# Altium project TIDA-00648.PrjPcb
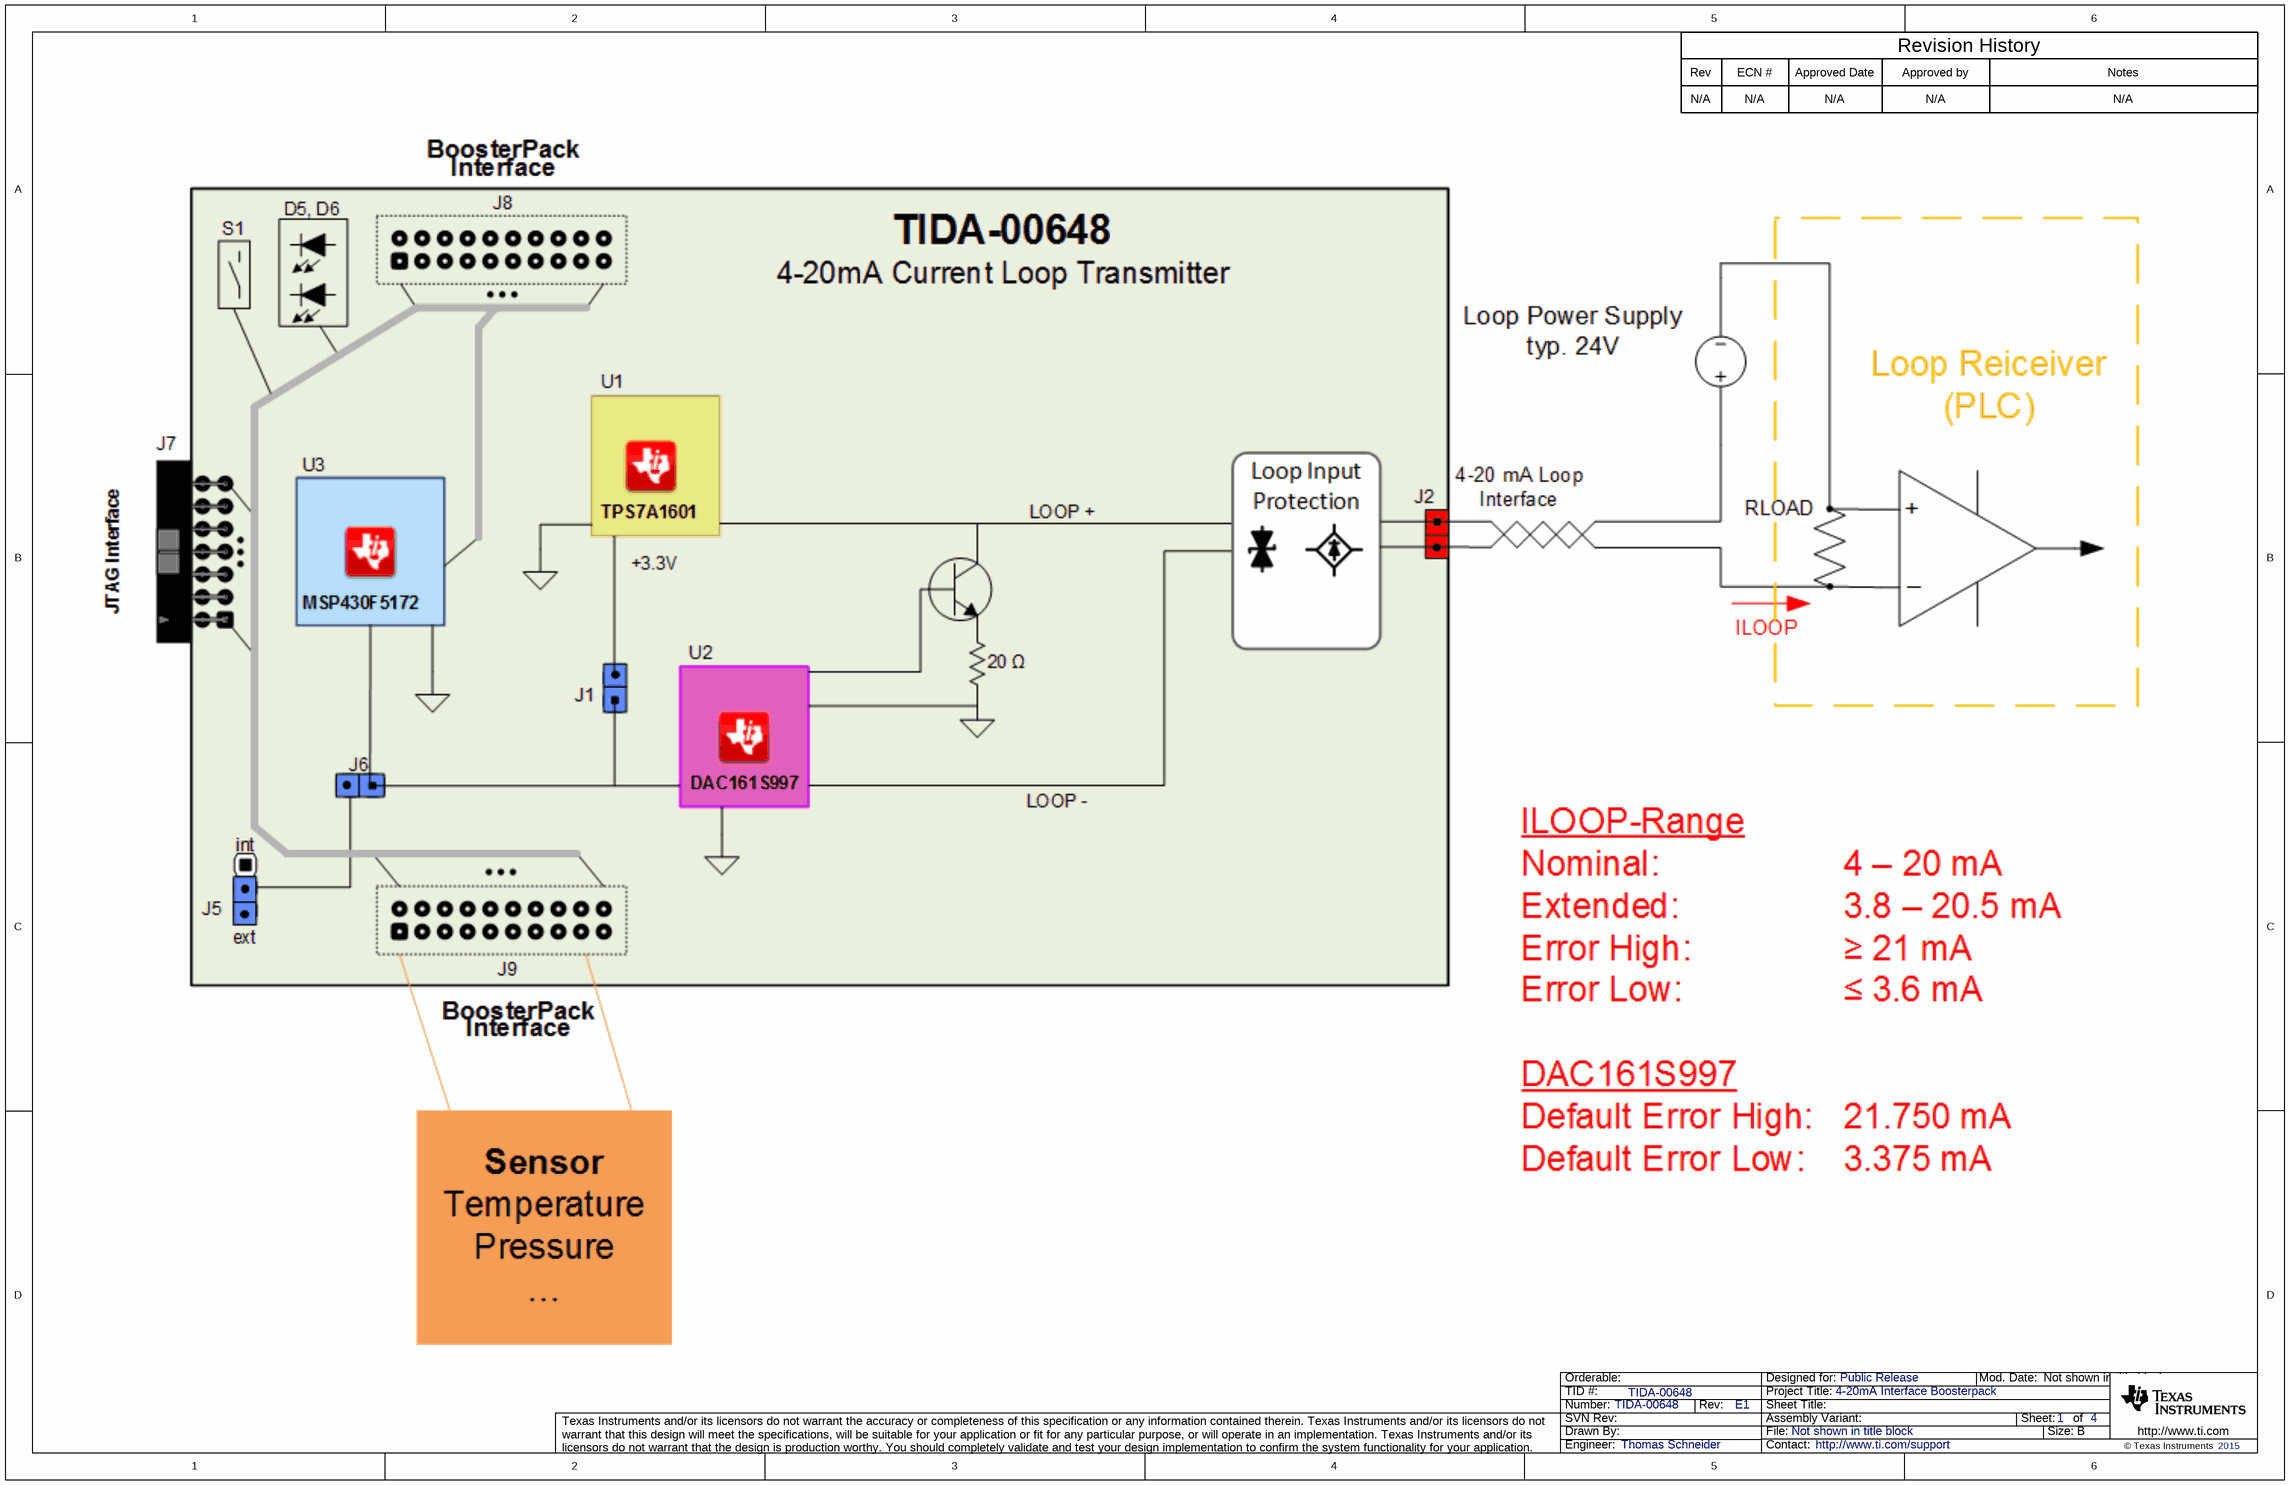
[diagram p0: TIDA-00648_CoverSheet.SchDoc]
CopyrightYear: 2015; PCB_Layout: Thomas Schneider; PCB_Rev: E1; PRJ_Customer: Public Release; PRJ_Engineer: Thomas Schneider; PRJ_Number: TIDA-00648; PRJ_Title: 4-20mA Interface Boosterpack; SCH_Rev: E1; TechSupport: http://www.ti.com/support; TID: TIDA-00648
4 sheets, 92 parts. Net scope: flat (ports and power ports of the same name join across sheets).
Board file: TIDA-00648_EVM.PcbDoc
Sheets:
  TIDA-00648_CoverSheet.SchDoc
  TIDA-00648_DAC.SchDoc
  TIDA-00648_Hardware.SchDoc
  TIDA-00648_MCU.SchDoc

## Sheet TIDA-00648_CoverSheet.SchDoc
size 431 x 279 mm; Date: Not shown in title block; ApprovedBy: Not shown in title block; CheckedBy: Not shown in title block; Author: Not shown in title block; CompanyName: Not shown in title block; Engineer: Not shown in title block; Organization: Not shown in title block; Address1: Not shown in title block; Address2: Not shown in title block; Address3: Not shown in title block; Address4: Not shown in title block; DocumentNumber: 1; Revision: Use project parameter SCH_Rev; SheetNumber: 1; SheetTotal: 4; PageSetup: Record=PageOptions¦CenterHorizontal=True¦CenterVertical=True¦PrintScale=1.00¦XCorrection=1.00¦YCorrection=1.00¦PrintKind=0¦BorderSize=5000000¦LeftOffset=0¦BottomOffset=0¦Orientation=2¦PaperLength=1000¦PaperWidth=1000¦Scale=100¦PaperSource=15¦PrintQuality=600¦MediaType=1¦DitherType=10¦PaperKind=Letter¦PrintScaleMode=1

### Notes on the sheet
- Rev
- N/A
- ECN #
- Approved Date
- Approved by
- Revision History
- Notes

## Sheet TIDA-00648_DAC.SchDoc
size 431 x 279 mm; Date: Not shown in title block; ApprovedBy: Not shown in title block; CheckedBy: Not shown in title block; Author: Not shown in title block; CompanyName: Not shown in title block; Engineer: Not shown in title block; Organization: Not shown in title block; Address1: Not shown in title block; Address2: Not shown in title block; Address3: Not shown in title block; Address4: Not shown in title block; DocumentNumber: 2; Revision: Use project parameter SCH_Rev; SheetNumber: 2; SheetTotal: 4; PageSetup: Record=PageOptions¦CenterHorizontal=True¦CenterVertical=True¦PrintScale=1.00¦XCorrection=1.00¦YCorrection=1.00¦PrintKind=0¦BorderSize=5000000¦LeftOffset=0¦BottomOffset=0¦Orientation=2¦PaperLength=1000¦PaperWidth=1000¦Scale=100¦PaperSource=15¦PrintQuality=600¦MediaType=1¦DitherType=10¦PaperKind=Letter¦PrintScaleMode=1
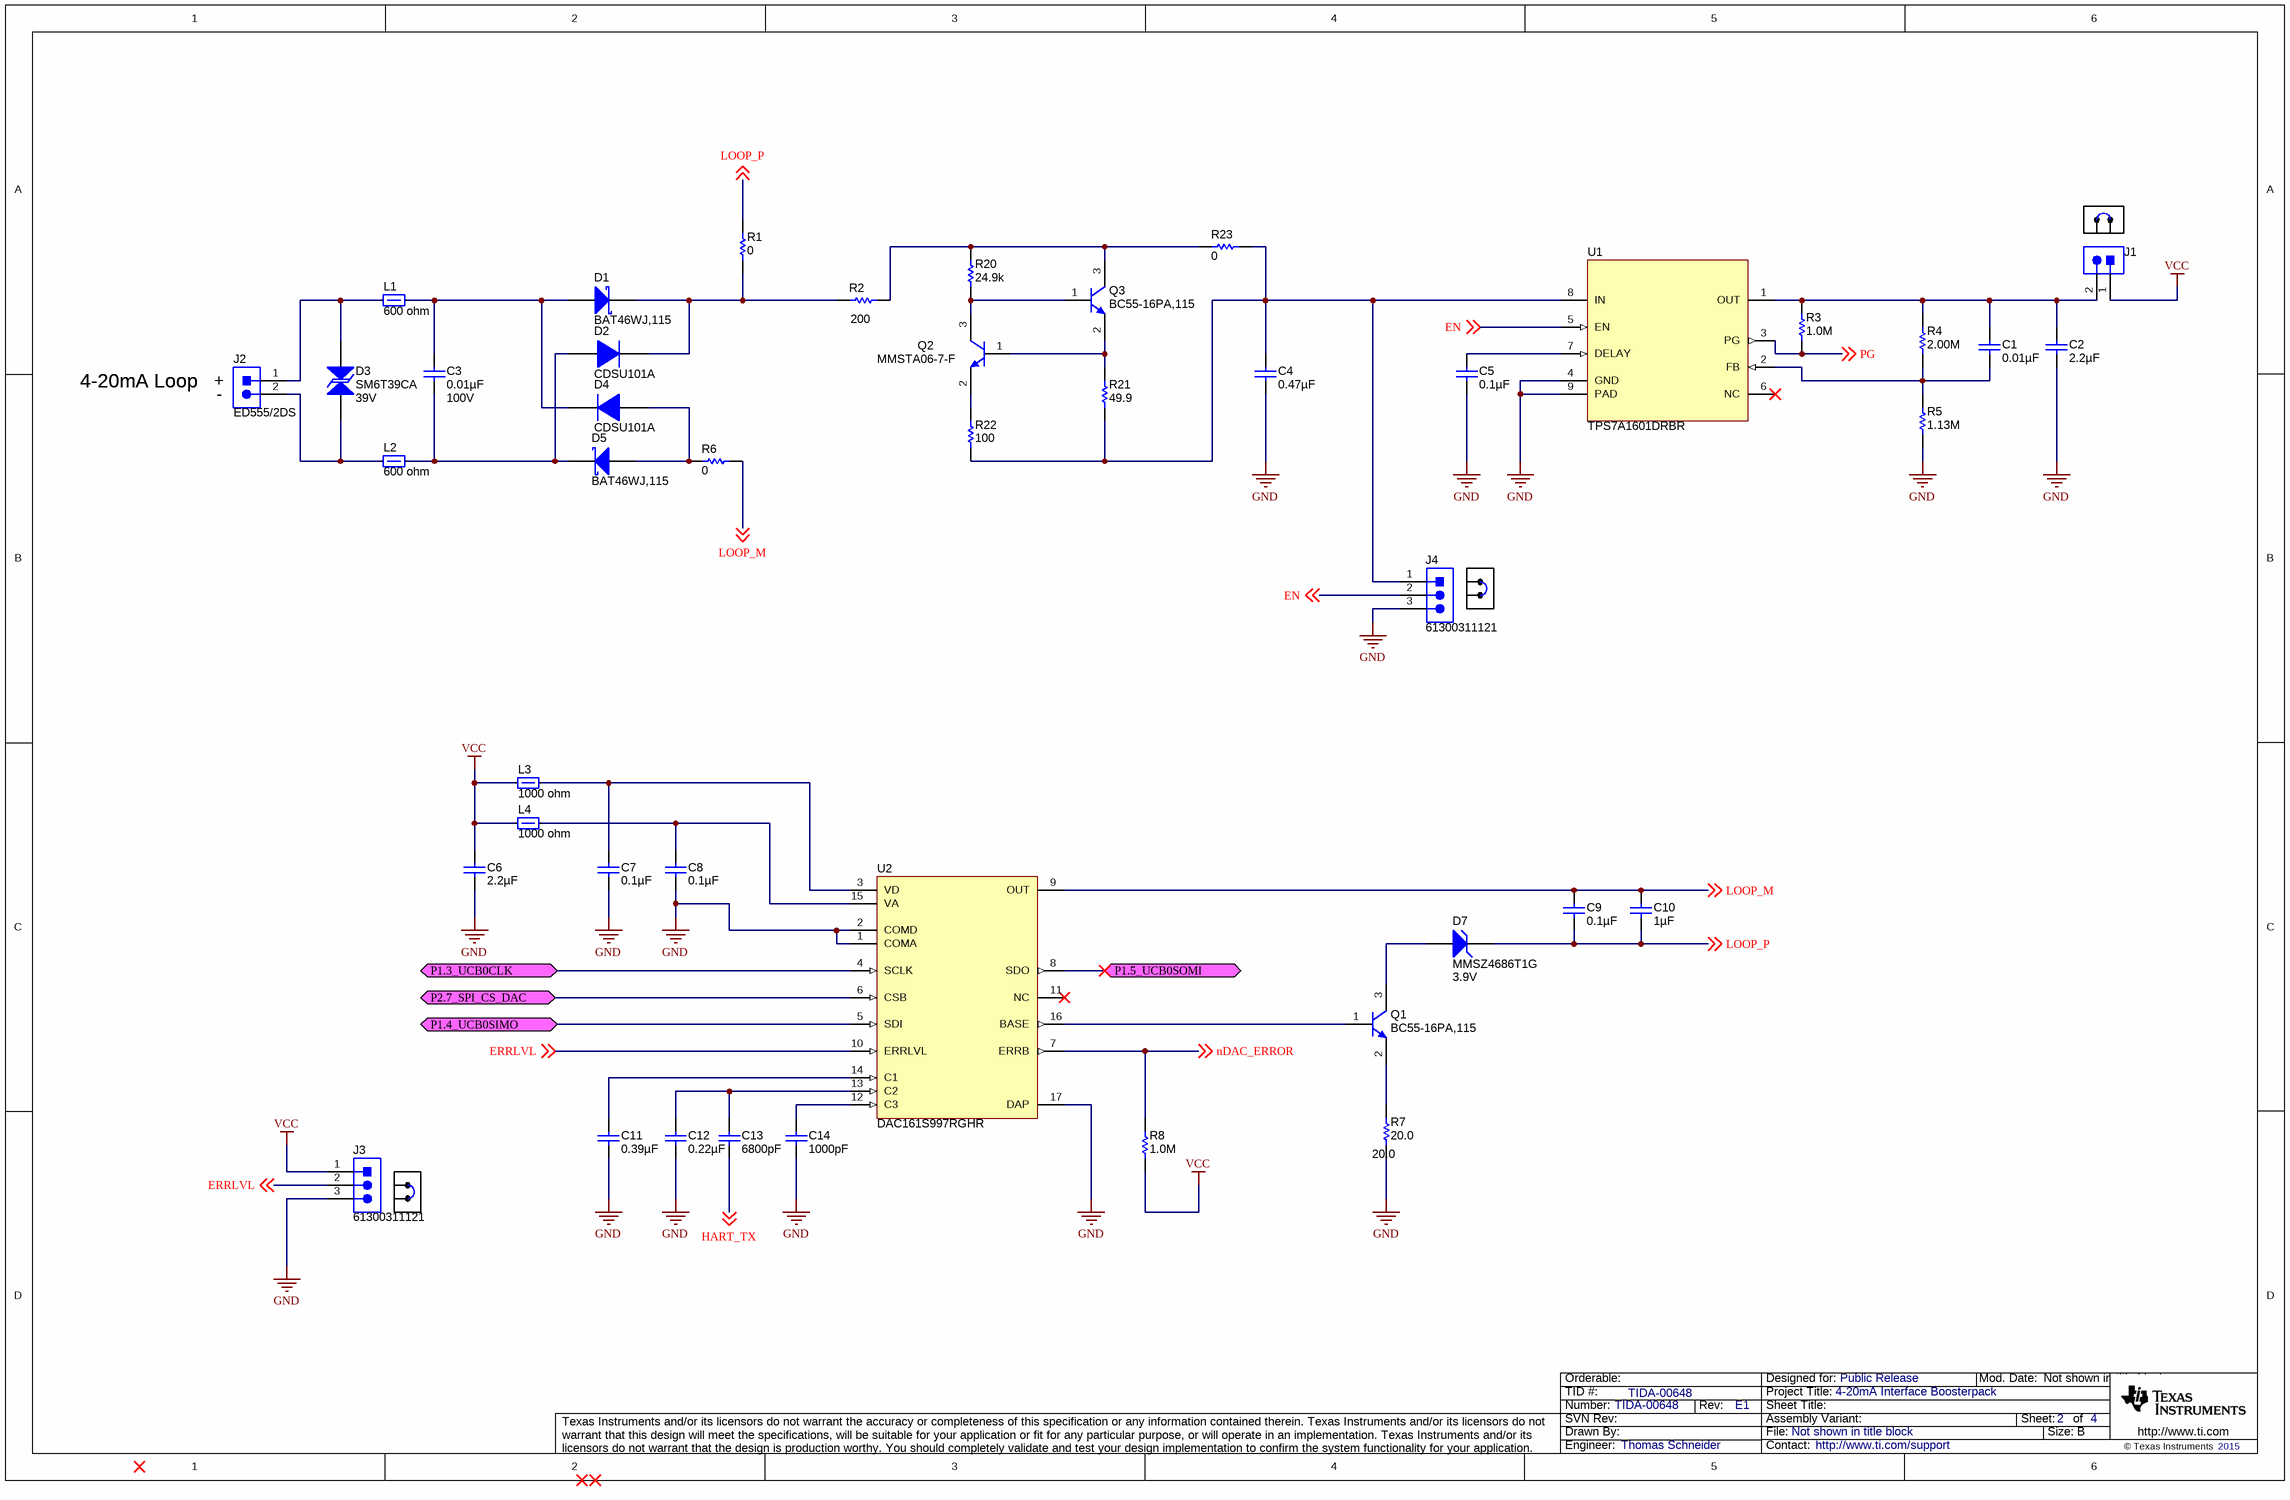
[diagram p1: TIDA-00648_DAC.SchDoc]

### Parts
C1  ValueDisplayed: 0.01µF  [0402]  (hidden comment: GRM155R61A103KA01D)
C2  ValueDisplayed: 2.2µF  [0402]  (hidden comment: C1005X5R1C225K050BC)
C3  ValueDisplayed: 0.01µF  Value2: 100V  [0603]  (hidden comment: C1608X7R2A103K)
C4  ValueDisplayed: 0.47µF  [0805]  (hidden comment: GRM21BR72A474KA73L)
C5  ValueDisplayed: 0.1µF  [0402]  (hidden comment: GRM155R61A104KA01D)
C6  ValueDisplayed: 2.2µF  [0402]  (hidden comment: C1005X5R1C225K050BC)
C7  ValueDisplayed: 0.1µF  [0402]  (hidden comment: C1005X5R0J104K)
C8  ValueDisplayed: 0.1µF  [0402]  (hidden comment: C1005X5R0J104K)
C9  ValueDisplayed: 0.1µF  [1206]  (hidden comment: 12061C104JAT2A)
C10  ValueDisplayed: 1µF  [1206]  (hidden comment: GRM31CR72A105KA01L)
C11  ValueDisplayed: 0.39µF  [0402]  (hidden comment: GRM155R61A394KE15D)
C12  ValueDisplayed: 0.22µF  [0402]  (hidden comment: GRM155R60J224KE01D)
C13  ValueDisplayed: 6800pF  [0402]  (hidden comment: GRM155R71E682KA01D)
C14  ValueDisplayed: 1000pF  [0402]  (hidden comment: GRM155R60J102KA01D)
D1  BAT46WJ,115  [SOD-323F]
D2  CDSU101A  [SOD-523F]
D3  SM6T39CA  value 39V  [SMB]
D4  CDSU101A  [SOD-523F]
D5  BAT46WJ,115  [SOD-323F]
D7  MMSZ4686T1G  value 3.9V  [SOD-123]
J1  61300211121  [WURTH_61300211121]  (value not drawn)
J2  ED555/2DS  [TERM_BLK_ED555-2DS]
J3  61300311121  [WURTH_61300311121]
J4  61300311121  [WURTH_61300311121]
L1  value 600 ohm  [1206]  (hidden comment: MI1206K601R-10)
L2  value 600 ohm  [1206]  (hidden comment: MI1206K601R-10)
L3  value 1000 ohm  [0402]  (hidden comment: BLM15HG102SN1D)
L4  value 1000 ohm  [0402]  (hidden comment: BLM15HG102SN1D)
Q1  BC55-16PA,115  [SOT1061]
Q2  MMSTA06-7-F  [SOT-323]
Q3  BC55-16PA,115  [SOT1061]
R1  ValueDisplayed: 0  [0603]  (hidden comment: CRCW06030000Z0EA)
R2  ValueDisplayed: 200  [1206]  (hidden comment: CRCW1206200RFKEA)
R3  ValueDisplayed: 1.0M  [0402]  (hidden comment: CRCW04021M00JNED)
R4  ValueDisplayed: 2.00M  [0402]  (hidden comment: CRCW04022M00FKED)
R5  ValueDisplayed: 1.13M  [0402]  (hidden comment: CRCW04021M13FKED)
R6  ValueDisplayed: 0  [0603]  (hidden comment: CRCW06030000Z0EA)
R7  value 20.0  [0603]  (hidden comment: CRCW060320R0FKEA)
R8  ValueDisplayed: 1.0M  [0402]  (hidden comment: CRCW04021M00JNED)
R20  ValueDisplayed: 24.9k  [0603]  (hidden comment: CRCW060324K9FKEA)
R21  ValueDisplayed: 49.9  [1206]  (hidden comment: CRCW120649R9FKEA)
R22  ValueDisplayed: 100  [0603]  (hidden comment: CRCW0603100RFKEA)
R23  ValueDisplayed: 0  [0603]  (hidden comment: CRCW06030000Z0EA)
SH-J1  969102-0000-DA  [SNT-100-BK-G]  (value not drawn)
SH-J2  969102-0000-DA  [SNT-100-BK-G]  (value not drawn)
SH-J3  969102-0000-DA  [SNT-100-BK-G]  (value not drawn)
U1  TPS7A1601DRBR  [DRB0008B]
U2  DAC161S997RGHR  [RGH0016A]

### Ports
P1.3_UCB0CLK (bidir), P1.4_UCB0SIMO (bidir), P1.5_UCB0SOMI (bidir), P2.7_SPI_CS_DAC (bidir)

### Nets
GND: C2.2 C4.2 C5.2 C6.2 C7.2 C8.2 C11.2 C12.2 C14.2 J3.3 J4.3 R5.1 R7.1 U1.4(GND) U1.9(PAD) U2.1(COMA) U2.2(COMD) U2.17(DAP)
VCC: C6.1 J1.1 J3.1 L3.1 L4.1 R8.1
EN: J4.2 U1.5(EN) ; off-sheet EN
ERRLVL: J3.2 U2.10(ERRLVL) ; off-sheet ERRLVL
HART_TX: C13.2 ; off-sheet HART_TX
LOOP_M: C9.2 C10.2 R6.1 U2.9(OUT) ; off-sheet LOOP_M
LOOP_P: C9.1 C10.1 D7.1(K) R1.2 ; off-sheet LOOP_P
nDAC_ERROR: R8.2 U2.7(ERRB) ; off-sheet nDAC_ERROR
P1.3_UCB0CLK: U2.4(SCLK) ; port P1.3_UCB0CLK
P1.4_UCB0SIMO: U2.5(SDI) ; port P1.4_UCB0SIMO
P1.5_UCB0SOMI: U2.8(SDO) ; port P1.5_UCB0SOMI
P2.7_SPI_CS_DAC: U2.6(CSB) ; port P2.7_SPI_CS_DAC
PG: R3.1 U1.3(PG) ; off-sheet PG
NetC1_1: C1.1 C2.1 J1.2 R3.2 R4.2 U1.1(OUT)
NetC1_2: C1.2 R4.1 R5.2 U1.2(FB)
NetC3_1: C3.1 D1.2(A) D4.1(K) L1.2
NetC3_2: C3.2 D2.2(A) D5.1(K) L2.2
NetC4_1: C4.1 J4.1 R21.1 R22.1 R23.2 U1.8(IN)
NetC5_1: C5.1 U1.7(DELAY)
NetC7_1: C7.1 L3.2 U2.3(VD)
NetC8_1: C8.1 L4.2 U2.15(VA)
NetC11_1: C11.1 U2.14(C1)
NetC12_1: C12.1 C13.1 U2.13(C2)
NetC14_1: C14.1 U2.12(C3)
NetD1_1: D1.1(K) D2.1(K) R1.1 R2.1
NetD3_1: D3.1 J2.1 L1.1
NetD3_2: D3.2 J2.2 L2.1
NetD4_2: D4.2(A) D5.2(A) R6.2
NetD7_2: D7.2(A) Q1.3(C)
NetQ1_1: Q1.1(B) U2.16(BASE)
NetQ1_2: Q1.2(E) R7.2
NetQ2_1: Q2.1(B) Q3.2(E) R21.2
NetQ2_2: Q2.2(E) R22.2
NetQ2_3: Q2.3(C) Q3.1(B) R20.1
NetQ3_3: Q3.3(C) R2.2 R20.2 R23.1

Not connected (* = marked no-connect by the designer): U1 6(NC)*; U2 11(NC)*

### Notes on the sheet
- 4-20mA Loop
- (near J2) +
- (near J2) -

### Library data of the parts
C1 = GRM155R61A103KA01D: CAP, CERM, 0.01 µF, 10 V, +/- 10%, X5R, 0402; Manufacturer: MuRata; Polarized: N; CompType: Capacitor; Value: 0.01uF; U/M: EA; Cap_F: 0.00000001; Tolerance_%: 10; Value1: Unknown; Value2: 10V; TaMin_C: -55; TaMax_C: 85; AEC Category: Q200
C2 C6 = C1005X5R1C225K050BC: CAP, CERM, 2.2 µF, 16 V, +/- 10%, X5R, 0402; Manufacturer: TDK; Polarized: N; CompType: Capacitor; Value: 2.2uF; U/M: EA; Cap_F: 0.0000022; Tolerance_%: 10; Value1: Unknown; VDC_V: 16; Value2: 16V; TaMin_C: -55; TaMax_C: 85; AEC Category: Q200
C3 = C1608X7R2A103K: CAP, CERM, 0.01 µF, 100 V, +/- 10%, X7R, 0603; Manufacturer: TDK; Polarized: N; CompType: Capacitor; Value: 0.01uF; U/M: EA; Cap_F: 0.00000001; Tolerance_%: 10; ESR_ohm: 0.0661; Value1: 0.0661 ohm; VDC_V: 100; TaMin_C: -55; TaMax_C: 125; AEC Category: Q200
C4 = GRM21BR72A474KA73L: CAP, CERM, 0.47 µF, 100 V, +/- 10%, X7R, 0805; Manufacturer: MuRata; Polarized: N; CompType: Capacitor; Value: 0.47uF; U/M: EA; Cap_F: 0.00000047; Tolerance_%: 10; Value1: Unknown; VDC_V: 100; Value2: 100V; TaMin_C: -55; TaMax_C: 125; AEC Category: Q200
C5 = GRM155R61A104KA01D: CAP, CERM, 0.1 µF, 10 V, +/- 10%, X5R, 0402; Manufacturer: MuRata; Polarized: N; CompType: Capacitor; Value: 0.1uF; U/M: EA; Cap_F: 0.0000001; Tolerance_%: 10; Value1: Unknown; Value2: 10V; TaMin_C: -55; TaMax_C: 85; AEC Category: Q200
C7 C8 = C1005X5R0J104K: CAP, CERM, 0.1 µF, 6.3 V, +/- 10%, X5R, 0402; Manufacturer: TDK; Polarized: N; CompType: Capacitor; Value: 0.1uF; U/M: EA; Cap_F: 0.0000001; Tolerance_%: 10; ESR_ohm: 0.0186; Value1: 0.0186 ohm; VDC_V: 6.3; Value2: 6.3V; TaMin_C: -55; TaMax_C: 85; AEC Category: Q200
C9 = 12061C104JAT2A: CAP, CERM, 0.1 µF, 100 V, +/- 5%, X7R, 1206; Manufacturer: AVX; Polarized: N; CompType: Capacitor; Value: 0.1uF; U/M: EA; Cap_F: 0.0000001; Tolerance_%: 5; ESR_ohm: 0.037; Value1: 0.037 ohm; VDC_V: 100; Value2: 100V; TaMin_C: -55; TaMax_C: 125; AEC Category: Q200
C10 = GRM31CR72A105KA01L: CAP, CERM, 1 µF, 100 V, +/- 10%, X7R, 1206; Manufacturer: MuRata; Polarized: N; CompType: Capacitor; Value: 1uF; U/M: EA; Cap_F: 0.000001; Tolerance_%: 10; Value1: Unknown; VDC_V: 100; Value2: 100V; TaMin_C: -55; TaMax_C: 125; Cap_Case: 2220; AEC Category: Q200
C11 = GRM155R61A394KE15D: CAP, CERM, 0.39 µF, 10 V, +/- 10%, X5R, 0402; Manufacturer: MuRata; Polarized: N; CompType: Capacitor; Value: 0.39uF; U/M: EA; Cap_F: 0.00000039; Tolerance_%: 10; Value1: Unknown; Value2: 10V; TaMin_C: -55; TaMax_C: 85; AEC Category: Q200
C12 = GRM155R60J224KE01D: CAP, CERM, 0.22 µF, 6.3 V, +/- 10%, X5R, 0402; Manufacturer: MuRata; Polarized: N; CompType: Capacitor; Value: 0.22uF; U/M: EA; Cap_F: 0.00000022; Tolerance_%: 10; Value1: Unknown; VDC_V: 6.3; Value2: 6.3V; TaMin_C: -55; TaMax_C: 85; AEC Category: Q200
C13 = GRM155R71E682KA01D: CAP, CERM, 6800 pF, 25 V, +/- 10%, X7R, 0402; Manufacturer: MuRata; Polarized: N; CompType: Capacitor; Value: 6800pF; U/M: EA; Cap_F: 0.0000000068; Tolerance_%: 10; Value1: Unknown; VDC_V: 25; Value2: 25V; TaMin_C: -55; TaMax_C: 125; AEC Category: Q200
C14 = GRM155R60J102KA01D: CAP, CERM, 1000 pF, 6.3 V, +/- 10%, X5R, 0402; Manufacturer: MuRata; Polarized: N; CompType: Capacitor; Value: 1000pF; U/M: EA; Cap_F: 0.000000001; Tolerance_%: 10; Value1: Unknown; VDC_V: 6.3; Value2: 6.3V; TaMin_C: -55; TaMax_C: 85; AEC Category: Q200
D1 D5 = BAT46WJ,115: Diode, Schottky, 100 V, 0.25 A, SOD-323F; Manufacturer: NXP Semiconductor; U/M: EA; Vf_V: 0.85; Value: 100V; Value1: 0.25A; Value2: 0.85V; Io_A: 0.25; Vr_V: 100; TJmax_C: 150; AEC Category: Q101
D2 D4 = CDSU101A: Diode, Switching, 90 V, 0.1 A, SOD-523F; Manufacturer: Comchip Technology; U/M: EA; Vf_V: 1; Value: 90V; Value1: 0.1A; Value2: 1V; Io_A: 0.1; Vr_V: 90; TJmax_C: 125; AEC Category: Q101
D3 = SM6T39CA: Diode, TVS, Bi, 39 V, 600 W, SMB; Manufacturer: STMicroelectronics; U/M: EA; Power_W: 600; Value1: 600W; RJA_CperW: 100; Vr_V: 39; AEC Category: Q101
D7 = MMSZ4686T1G: Diode, Zener, 3.9 V, 500 mW, SOD-123; Manufacturer: ON Semiconductor; U/M: EA; Power_W: 0.5; Vz_V: 3.9; Value1: 0.5W; RJA_CperW: 340; SymbolCreator: a0412235; AEC Category: Q101
J1 = 61300211121: Header, 2.54 mm, 2x1, Gold, TH; Manufacturer: Wurth Elektronik; SymbolCreator: a0412235; U/M: EA
J2 = ED555/2DS: Terminal Block, 6A, 3.5mm Pitch, 2-Pos, TH; Manufacturer: On-Shore Technology; SymbolCreator: a0412235; CompType: Connector; U/M: EA
J3 J4 = 61300311121: Header, 2.54 mm, 3x1, Gold, TH; Manufacturer: Wurth Elektronik; SymbolCreator: a0799628; U/M: EA
L1 L2 = MI1206K601R-10: Ferrite Bead, 600 ohm @ 100 MHz, 1.5 A, 1206; Manufacturer: Laird-Signal Integrity Products; Imax_A: 1.5; DCR_ohm: 0.08; Value1: 0.08 ohm; Value2: 1.5A; ZTyp@100MHz_Ohm: 600; Ztyp@1GHz_Ohm: 130
L3 L4 = BLM15HG102SN1D: Ferrite Bead, 1000 ohm @ 100 MHz, 0.25 A, 0402; Manufacturer: MuRata; Imax_A: 0.25; DCR_ohm: 1.1; Value1: 1.1 ohm; Value2: 0.25A; ZTyp@100MHz_Ohm: 1000
Q1 = BC55-16PA,115, NXP Semiconductor: Transistor, NPN, 60 V, 1 A, AEC-Q101, SOT1061; PNP: 0; NPN: 1; Vceo_V: 60; Vcesat1_V: 0.5; Value: 60 V; Value1: 1 A; HfeMax: 250; TaMin_C: -55; TaMax_C: 150; CompType: BJT; U/M: EA; AEC Category: Q101; AEC Qualified: Y
Q2 = MMSTA06-7-F, Diodes Inc.: Transistor, NPN, 80 V, 0.5 A, SOT-323; CompType: BJT; PNP: 0; NPN: 1; Vceo_V: 80; Vcesat1_V: 0.25; Value: 80 V; IcRated_A: 0.5; Value1: 0.5 A; TaMin_C: -55; TaMax_C: 150; U/M: EA; AEC Category: Q101
Q3 = BC55-16PA,115, NXP Semiconductor: Transistor, NPN, 60 V, 1 A, AEC-Q101, SOT1061; CompType: BJT; PNP: 0; NPN: 1; Vceo_V: 60; Vcesat1_V: 0.5; Value: 60 V; Value1: 1 A; HfeMax: 250; TaMin_C: -55; TaMax_C: 150; U/M: EA; AEC Category: Q101; AEC Qualified: Y
R1 R6 R23 = CRCW06030000Z0EA: RES, 0, 5%, 0.1 W, 0603; Manufacturer: Vishay-Dale; CompType: Resistor; Value: 0; Value_Code: 0000; Tolerance_%: 5; Power_W: 0.1; Value2: 0.1W; VDC_V: 75; TempCo: 200 ppm/C; EIA_Code: E24; U/M: EA; AEC Category: Q200
R2 = CRCW1206200RFKEA: RES, 200, 1%, 0.25 W, 1206; Manufacturer: Vishay-Dale; CompType: Resistor; Value: 200; Value_Code: 200R; Tolerance_%: 1; Power_W: 0.25; Value2: 0.25W; TempCo: 100 ppm/C; EIA_Code: E96; U/M: EA; AEC Category: Q200
R3 R8 = CRCW04021M00JNED: RES, 1.0 M, 5%, 0.063 W, 0402; Manufacturer: Vishay-Dale; CompType: Resistor; Value: 1.0Meg; Res_ohm: 1000000; Value_Code: 1M00; Tolerance_%: 5; Power_W: 0.063; Value2: 0.063W; VDC_V: 50; TempCo: 200 ppm/C; EIA_Code: E24; U/M: EA; AEC Category: Q200
R4 = CRCW04022M00FKED: RES, 2.00 M, 1%, 0.063 W, 0402; Manufacturer: Vishay-Dale; CompType: Resistor; Value: 2.00Meg; Res_ohm: 2000000; Value_Code: 2M00; Tolerance_%: 1; Power_W: 0.063; Value2: 0.063W; VDC_V: 50; TempCo: 100 ppm/C; EIA_Code: E96; U/M: EA; AEC Category: Q200
R5 = CRCW04021M13FKED: RES, 1.13 M, 1%, 0.063 W, 0402; Manufacturer: Vishay-Dale; CompType: Resistor; Value: 1.13Meg; Res_ohm: 1130000; Value_Code: 1M13; Tolerance_%: 1; Power_W: 0.063; Value2: 0.063W; VDC_V: 50; TempCo: 100 ppm/C; EIA_Code: E96; U/M: EA; AEC Category: Q200
R7 = CRCW060320R0FKEA: RES, 20.0, 1%, 0.1 W, 0603; Manufacturer: Vishay-Dale; CompType: Resistor; Res_ohm: 20; Value_Code: 20R0; Tolerance_%: 1; Power_W: 0.1; Value2: 0.1W; VDC_V: 75; TempCo: 100 ppm/C; EIA_Code: E96; U/M: EA; AEC Category: Q200
R20 = CRCW060324K9FKEA: RES, 24.9 k, 1%, 0.1 W, 0603; Manufacturer: Vishay-Dale; CompType: Resistor; Value: 24.9k; Res_ohm: 24900; Value_Code: 24k9; Tolerance_%: 1; Power_W: 0.1; Value2: 0.1W; VDC_V: 75; TempCo: 100 ppm/C; EIA_Code: E96; U/M: EA; AEC Category: Q200
R21 = CRCW120649R9FKEA: RES, 49.9, 1%, 0.25 W, 1206; Manufacturer: Vishay-Dale; CompType: Resistor; Value: 49.9; Value_Code: 49R9; Tolerance_%: 1; Power_W: 0.25; Value2: 0.25W; VDC_V: 200; TempCo: 100 ppm/C; EIA_Code: E96; U/M: EA; AEC Category: Q200
R22 = CRCW0603100RFKEA: RES, 100, 1%, 0.1 W, 0603; Manufacturer: Vishay-Dale; CompType: Resistor; Value: 100; Value_Code: 100R; Tolerance_%: 1; Power_W: 0.1; Value2: 0.1W; VDC_V: 75; TempCo: 100 ppm/C; EIA_Code: E96; U/M: EA; AEC Category: Q200
SH-J1-SH-J3 = 969102-0000-DA: Shunt, 100mil, Gold plated, Black; Manufacturer: 3M; Alternate Manufacturer: Samtec; Value: 1x2; Note: You can "mate" this to a header by matching the designator.  i.e. use SH-J3 for header J3
U1 = TPS7A1601DRBR: 60-V, 5-μA IQ, 100-mA, Low-Dropout Voltage Regulator with Enable and Power-Good, DRB0008B; Alternate Manufacturer: Texas Instruments; Alternate PartNumber: TPS7A1601DRBT; SymbolCreator: a0411947; CompType: IC; U/M: EA
U2 = DAC161S997RGHR: 16-bit SPI Programmable DAC for 4-20mA Loops, RGH0016A; Alternate Manufacturer: Texas Instruments; Alternate PartNumber: DAC161S997RGHT; SymbolCreator: x0208325; CompType: IC; U/M: EA

## Sheet TIDA-00648_Hardware.SchDoc
size 431 x 279 mm; Date: Not shown in title block; ApprovedBy: Not shown in title block; CheckedBy: Not shown in title block; Author: Not shown in title block; CompanyName: Not shown in title block; Engineer: Not shown in title block; Organization: Not shown in title block; Address1: Not shown in title block; Address2: Not shown in title block; Address3: Not shown in title block; Address4: Not shown in title block; DocumentNumber: 4; Revision: Use project parameter SCH_Rev; SheetNumber: 4; SheetTotal: 4; PageSetup: Record=PageOptions¦CenterHorizontal=True¦CenterVertical=True¦PrintScale=1.00¦XCorrection=1.00¦YCorrection=1.00¦PrintKind=0¦BorderSize=5000000¦LeftOffset=0¦BottomOffset=0¦Orientation=2¦PaperLength=1000¦PaperWidth=1000¦Scale=100¦PaperSource=15¦PrintQuality=600¦MediaType=1¦DitherType=10¦PaperKind=Letter¦PrintScaleMode=1
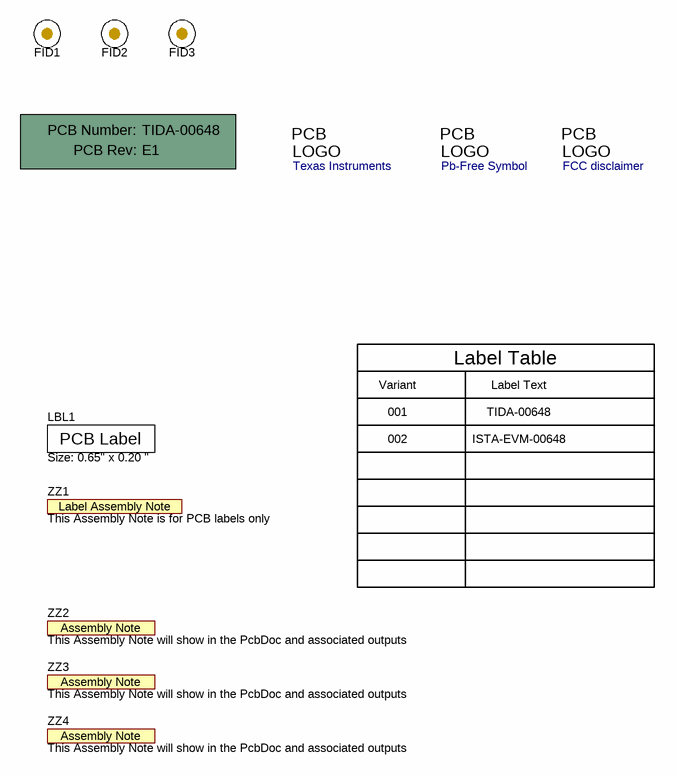
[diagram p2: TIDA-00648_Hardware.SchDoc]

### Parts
!PCB1  Printed Circuit Board  (value not drawn)  (mechanical)
FID1  Fiducial  [Fiducial10-20]  (value not drawn)
FID2  Fiducial  [Fiducial10-20]  (value not drawn)
FID3  Fiducial  [Fiducial10-20]  (value not drawn)
LBL1  Size: 0.65" x 0.20 "  [Label_650x200]
Logo1  Texas Instruments  [TI_Symbol_Overlay_Small]  (no BOM)
Logo2  Pb-Free Symbol  [Pb-Free_Overlay_Small]  (no BOM)
Logo3  FCC disclaimer  [FCC_disclaimer]  (no BOM)
ZZ1  This Assembly Note is for PCB labels only  [AssemblyNoteLabel]  (no BOM)
ZZ2  This Assembly Note will show in the PcbDoc and associated outputs  [AssemblyNote]  (no BOM)
ZZ3  This Assembly Note will show in the PcbDoc and associated outputs  [AssemblyNote]  (no BOM)
ZZ4  This Assembly Note will show in the PcbDoc and associated outputs  [AssemblyNote]  (no BOM)

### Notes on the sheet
- Variant
- Label Table
- Label Text
- 001
- 002
- TIDA-00648
- ISTA-EVM-00648

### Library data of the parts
!PCB1 = PCB: Manufacturer: Any; PartNumber: TIDA-00648; SymbolCreator: a0412235
FID1-FID3 = Fiducial: Fiducial mark.  There is nothing to buy or mount.; SymbolCreator: codlsc
LBL1 = THT-14-423-10: Thermal Transfer Printable Labels, 0.650" W x 0.200" H - 10,000 per roll; Manufacturer: Brady; SymbolCreator: a0412235; CompType: Label
Logo1 = TI_Logo: Texas Instrument Corporate Signature; SymbolCreator: a0412235
Logo2 = Pb-Free: SymbolCreator: a0412235
Logo3 = FCC_disclaimer: SymbolCreator: codlsc
ZZ1 = AssemblyNoteLabel: SymbolCreator: a0412235
ZZ2-ZZ4 = AssemblyNote: SymbolCreator: codlsc

## Sheet TIDA-00648_MCU.SchDoc
size 431 x 279 mm; Date: Not shown in title block; ApprovedBy: Not shown in title block; CheckedBy: Not shown in title block; Author: Not shown in title block; CompanyName: Not shown in title block; Engineer: Not shown in title block; Organization: Not shown in title block; Address1: Not shown in title block; Address2: Not shown in title block; Address3: Not shown in title block; Address4: Not shown in title block; DocumentNumber: 3; Revision: Use project parameter SCH_Rev; SheetNumber: 3; SheetTotal: 4; PageSetup: Record=PageOptions¦CenterHorizontal=True¦CenterVertical=True¦PrintScale=1.00¦XCorrection=1.00¦YCorrection=1.00¦PrintKind=0¦BorderSize=5000000¦LeftOffset=0¦BottomOffset=0¦Orientation=2¦PaperLength=1000¦PaperWidth=1000¦Scale=100¦PaperSource=15¦PrintQuality=600¦MediaType=1¦DitherType=10¦PaperKind=Letter¦PrintScaleMode=1
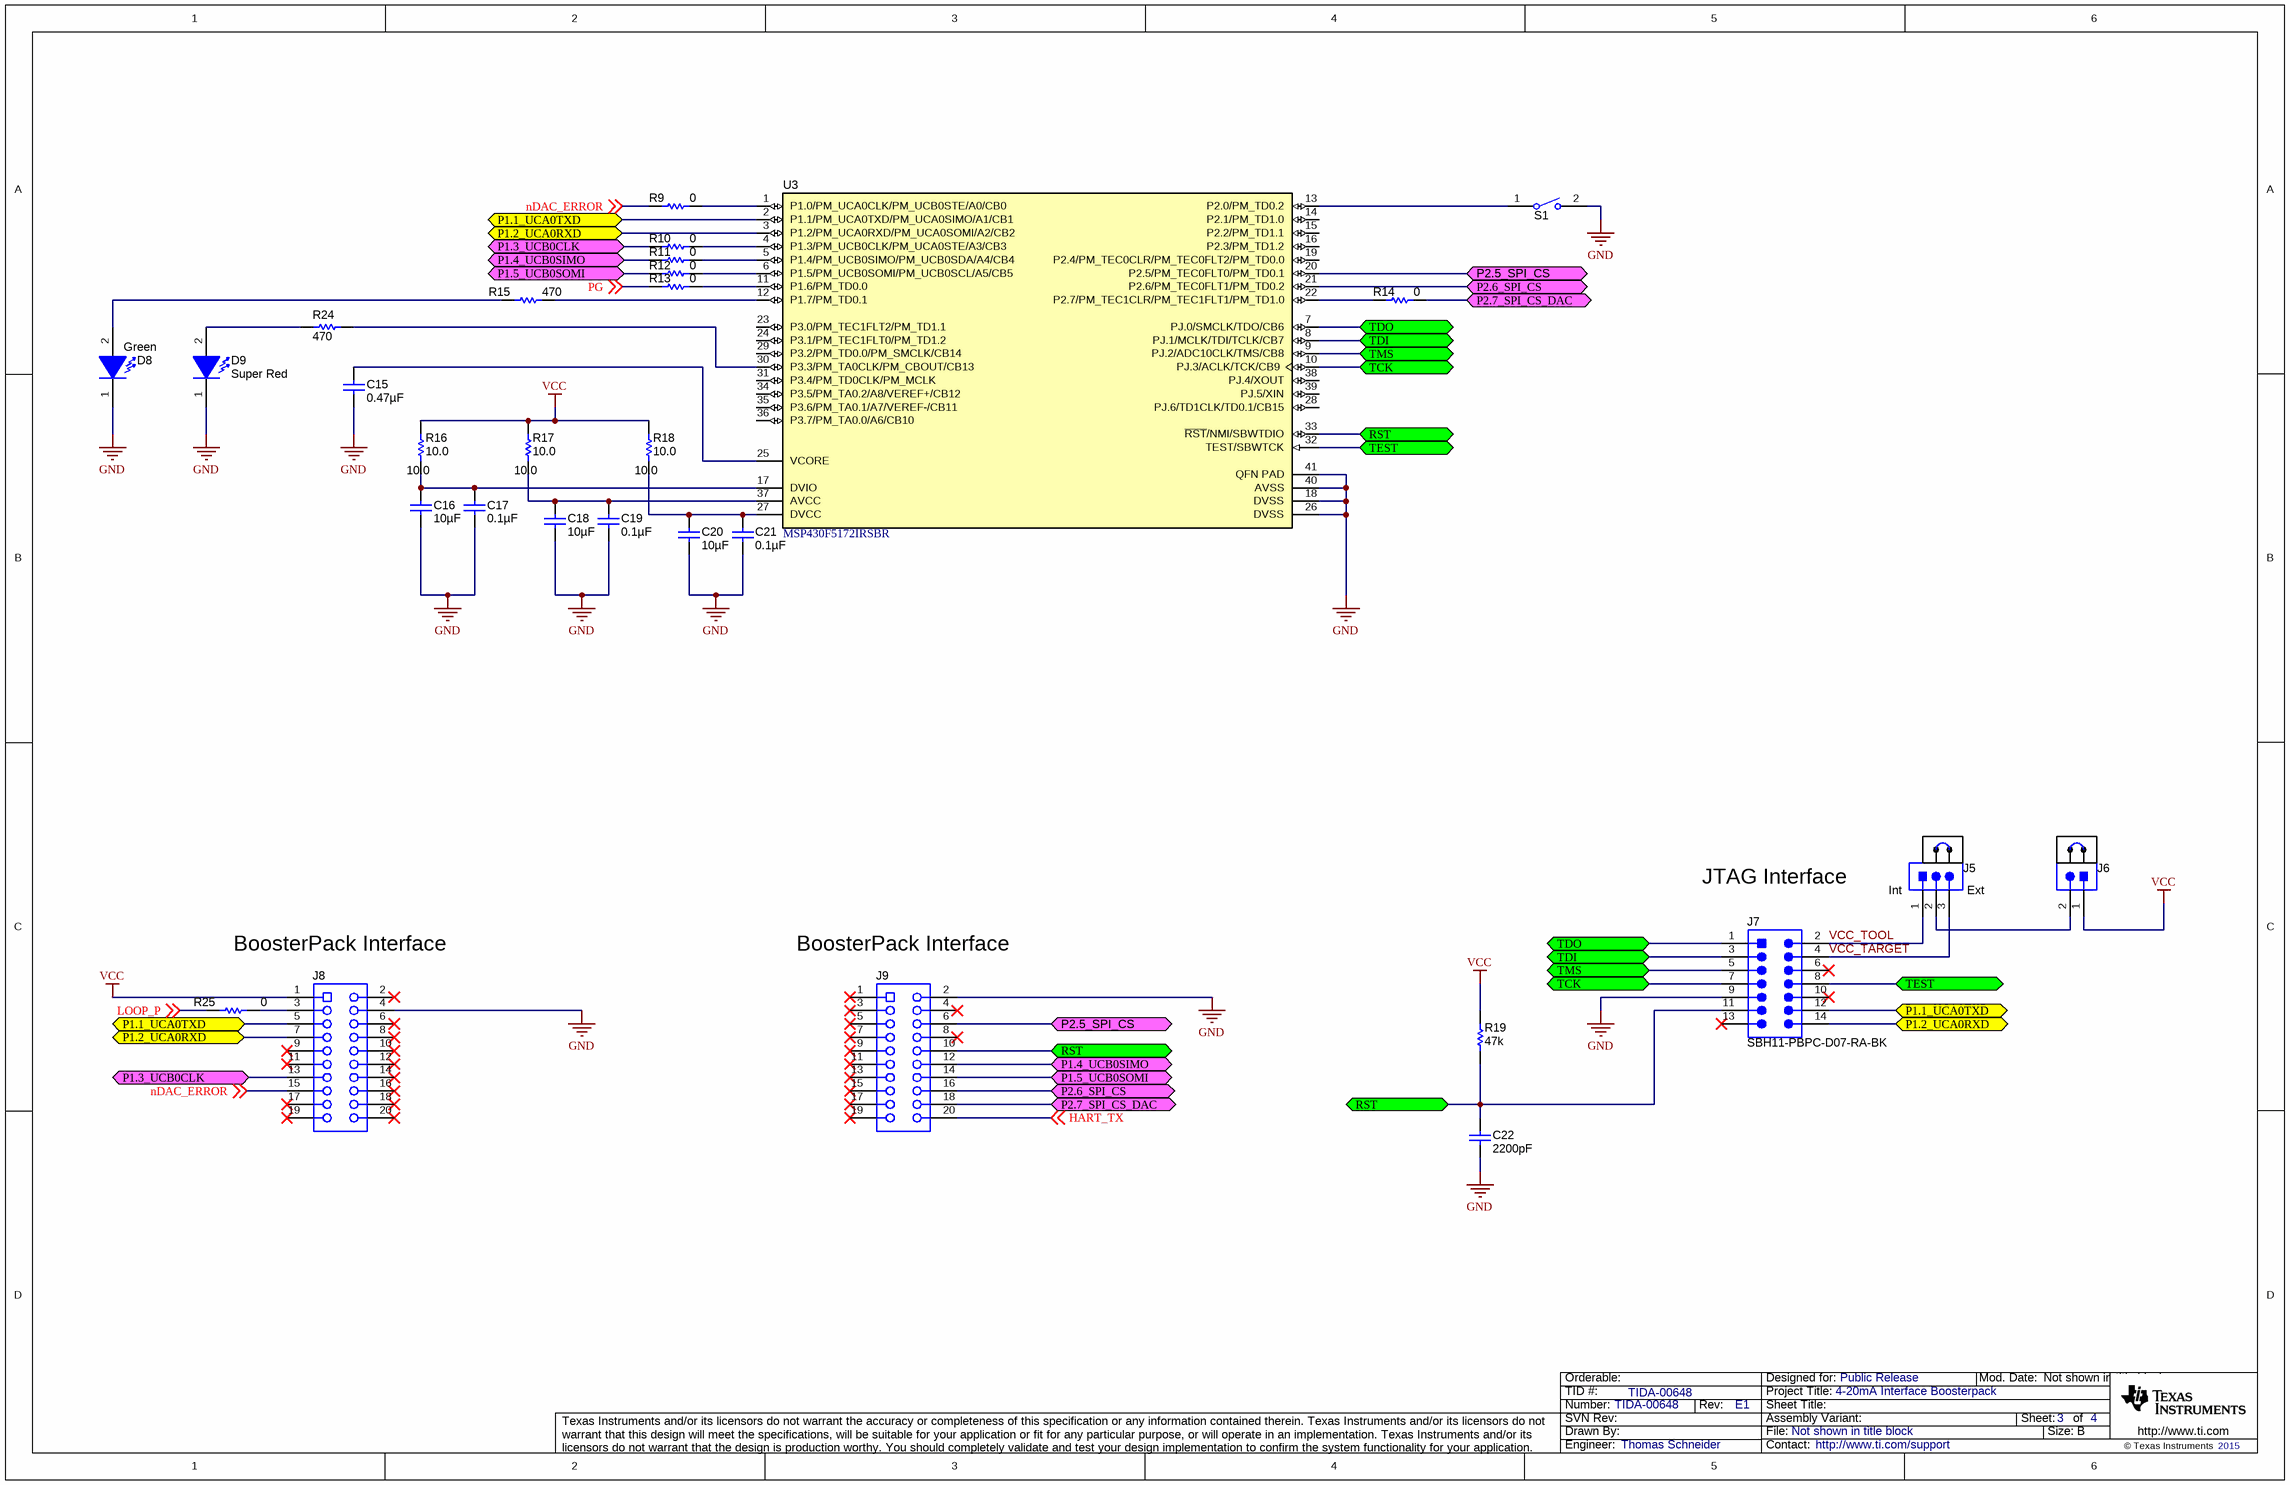
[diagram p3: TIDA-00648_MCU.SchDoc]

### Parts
C15  ValueDisplayed: 0.47µF  [0603S]  (hidden comment: GRM188R70J474KA01D)
C16  ValueDisplayed: 10µF  [0805]  (hidden comment: GRM21BR61C106KE15L)
C17  ValueDisplayed: 0.1µF  [0402]  (hidden comment: GRM155R71A104KA01D)
C18  ValueDisplayed: 10µF  [0805]  (hidden comment: GRM21BR61C106KE15L)
C19  ValueDisplayed: 0.1µF  [0402]  (hidden comment: GRM155R71A104KA01D)
C20  ValueDisplayed: 10µF  [0805]  (hidden comment: GRM21BR61C106KE15L)
C21  ValueDisplayed: 0.1µF  [0402]  (hidden comment: GRM155R71A104KA01D)
C22  ValueDisplayed: 2200pF  [0402]  (hidden comment: GRM155R70J222KA01D)
D8  value Green  [WL-SMCW_GREEN]  (hidden comment: 150060VS75000)
D9  value Super Red  [WL-SMCW_RED]  (hidden comment: 150060SS75000)
J5  61300311121  [WURTH_61300311121]  (value not drawn)
J6  61300211121  [WURTH_61300211121]  (value not drawn)
J7  SBH11-PBPC-D07-RA-BK  [Sullins_SBH11-PBPC-D07-RA-BK]
J8  SSW-110-23-F-D  [CONN_SSW-110-23-F-D]  (value not drawn)
J9  SSW-110-23-F-D  [CONN_SSW-110-23-F-D]  (value not drawn)
R9  ValueDisplayed: 0  [0402]  (hidden comment: CRCW04020000Z0ED)
R10  ValueDisplayed: 0  [0402]  (hidden comment: CRCW04020000Z0ED)
R11  ValueDisplayed: 0  [0402]  (hidden comment: CRCW04020000Z0ED)
R12  ValueDisplayed: 0  [0402]  (hidden comment: CRCW04020000Z0ED)
R13  ValueDisplayed: 0  [0402]  (hidden comment: CRCW04020000Z0ED)
R14  ValueDisplayed: 0  [0402]  (hidden comment: CRCW04020000Z0ED)
R15  ValueDisplayed: 470  [0402]  (hidden comment: CRCW0402470RJNED)
R16  value 10.0  [0603]  (hidden comment: CRCW060310R0FKEA)
R17  value 10.0  [0603]  (hidden comment: CRCW060310R0FKEA)
R18  value 10.0  [0603]  (hidden comment: CRCW060310R0FKEA)
R19  ValueDisplayed: 47k  [0402]  (hidden comment: CRCW040247K0JNED)
R24  ValueDisplayed: 470  [0402]  (hidden comment: CRCW0402470RJNED)
R25  ValueDisplayed: 0  [0603]  (hidden comment: CRCW06030000Z0EA)
S1  434121025816  [SW_434121025816]  (value not drawn)
SH-J4  969102-0000-DA  [SNT-100-BK-G]  (value not drawn)
SH-J5  969102-0000-DA  [SNT-100-BK-G]  (value not drawn)
U3  MSP430F5172IRSBR  [RSB0040B]

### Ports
P1.1_UCA0TXD (bidir), P1.2_UCA0RXD (bidir), P1.3_UCB0CLK (bidir), P1.4_UCB0SIMO (bidir), P1.5_UCB0SOMI (bidir), P2.5_SPI_CS (bidir), P2.6_SPI_CS (bidir), P2.7_SPI_CS_DAC (bidir), RST (bidir), TCK (bidir), TDI (bidir), TDO (bidir), TEST (bidir), TMS (bidir)

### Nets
GND: C15.2 C16.2 C17.1 C18.2 C19.1 C20.2 C21.1 C22.2 D8.1(K) D9.1(K) J7.9 J8.4 J9.2 S1.2 U3.18(DVSS) U3.26(DVSS) U3.40(AVSS) U3.41(QFN_PAD)
VCC: J6.1 J8.1 R16.2 R17.2 R18.2 R19.2
HART_TX: J9.20 ; off-sheet HART_TX
LOOP_P: R25.1 ; off-sheet LOOP_P
nDAC_ERROR: J8.15 R9.1 ; off-sheet nDAC_ERROR
P1.1_UCA0TXD: J7.12 J8.5 U3.2(P1.1/PM_UCA0TXD/PM_UCA0SIMO/A1/CB1) ; port P1.1_UCA0TXD
P1.2_UCA0RXD: J7.14 J8.7 U3.3(P1.2/PM_UCA0RXD/PM_UCA0SOMI/A2/CB2) ; port P1.2_UCA0RXD
P1.3_UCB0CLK: J8.13 R10.1 ; port P1.3_UCB0CLK
P1.4_UCB0SIMO: J9.12 R11.1 ; port P1.4_UCB0SIMO
P1.5_UCB0SOMI: J9.14 R12.1 ; port P1.5_UCB0SOMI
P2.5_SPI_CS: J9.6 U3.20(P2.5/PM_TEC0FLT0/PM_TD0.1) ; port P2.5_SPI_CS
P2.6_SPI_CS: J9.16 U3.21(P2.6/PM_TEC0FLT1/PM_TD0.2) ; port P2.6_SPI_CS
P2.7_SPI_CS_DAC: J9.18 R14.2 ; port P2.7_SPI_CS_DAC
PG: R13.1 ; off-sheet PG
RST: C22.1 J7.11 J9.10 R19.1 U3.33(~{RST}/NMI/SBWTDIO) ; port RST
TCK: J7.7 U3.10(PJ.3/ACLK/TCK/CB9) ; port TCK
TDI: J7.3 U3.8(PJ.1/MCLK/TDI/TCLK/CB7) ; port TDI
TDO: J7.1 U3.7(PJ.0/SMCLK/TDO/CB6) ; port TDO
TEST: J7.8 U3.32(TEST/SBWTCK) ; port TEST
TMS: J7.5 U3.9(PJ.2/ADC10CLK/TMS/CB8) ; port TMS
VCC_TARGET: J5.3 J7.4
VCC_TOOL: J5.1 J7.2
NetC15_1: C15.1 U3.25(VCORE)
NetC16_1: C16.1 C17.2 R16.1 U3.17(DVIO)
NetC18_1: C18.1 C19.2 R17.1 U3.37(AVCC)
NetC20_1: C20.1 C21.2 R18.1 U3.27(DVCC)
NetD8_2: D8.2(A) R15.1
NetD9_2: D9.2(A) R24.1
NetJ5_2: J5.2 J6.2
NetJ8_3: J8.3 R25.2
NetR9_2: R9.2 U3.1(P1.0/PM_UCA0CLK/PM_UCB0STE/A0/CB0)
NetR10_2: R10.2 U3.4(P1.3/PM_UCB0CLK/PM_UCA0STE/A3/CB3)
NetR11_2: R11.2 U3.5(P1.4/PM_UCB0SIMO/PM_UCB0SDA/A4/CB4)
NetR12_2: R12.2 U3.6(P1.5/PM_UCB0SOMI/PM_UCB0SCL/A5/CB5)
NetR13_2: R13.2 U3.11(P1.6/PM_TD0.0)
NetR14_1: R14.1 U3.22(P2.7/PM_TEC1CLR/PM_TEC1FLT1/PM_TD1.0)
NetR15_2: R15.2 U3.12(P1.7/PM_TD0.1)
NetR24_2: R24.2 U3.30(P3.3/PM_TA0CLK/PM_CBOUT/CB13)
NetS1_1: S1.1 U3.13(P2.0/PM_TD0.2)

Not connected (* = marked no-connect by the designer): J7 6* 10* 13*; J8 2* 6* 8* 9* 10* 11* 12* 14* 16* 17* 18* 19* 20*; J9 1* 3* 4* 5* 7* 8* 9* 11* 13* 15* 17* 19*; U3 14(P2.1/PM_TD1.0) 15(P2.2/PM_TD1.1) 16(P2.3/PM_TD1.2) 19(P2.4/PM_TEC0CLR/PM_TEC0FLT2/PM_TD0.0) 23(P3.0/PM_TEC1FLT2/PM_TD1.1) 24(P3.1/PM_TEC1FLT0/PM_TD1.2) 28(PJ.6/TD1CLK/TD0.1/CB15) 29(P3.2/PM_TD0.0/PM_SMCLK/CB14) 31(P3.4/PM_TD0CLK/PM_MCLK) 34(P3.5/PM_TA0.2/A8/VEREF+/CB12) 35(P3.6/PM_TA0.1/A7/VEREF-/CB11) 36(P3.7/PM_TA0.0/A6/CB10) 38(PJ.4/XOUT) 39(PJ.5/XIN)

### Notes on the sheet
- JTAG Interface
- (near J5) Int
- (near J5) Ext
- BoosterPack Interface
- (near J9) BoosterPack Interface

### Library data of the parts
C15 = GRM188R70J474KA01D: CAP, CERM, 0.47 µF, 6.3 V, +/- 10%, X7R, 0603; Manufacturer: MuRata; Polarized: N; CompType: Capacitor; Value: 0.47uF; U/M: EA; Cap_F: 0.00000047; Tolerance_%: 10; Value1: Unknown; VDC_V: 6.3; Value2: 6.3V; TaMin_C: -55; TaMax_C: 125; Cap_Case: 0603; AEC Category: Q200
C16 C18 C20 = GRM21BR61C106KE15L: CAP, CERM, 10 µF, 16 V, +/- 10%, X5R, 0805; Manufacturer: MuRata; Polarized: N; CompType: Capacitor; Value: 10uF; U/M: EA; Cap_F: 0.00001; Tolerance_%: 10; ESR_ohm: 0.008; Value1: 0.008 ohm; VDC_V: 16; Value2: 16V; TaMin_C: -55; TaMax_C: 85; AEC Category: Q200
C17 C19 C21 = GRM155R71A104KA01D: CAP, CERM, 0.1 µF, 10 V, +/- 10%, X7R, 0402; Manufacturer: MuRata; Polarized: N; CompType: Capacitor; Value: 0.1uF; U/M: EA; Cap_F: 0.0000001; Tolerance_%: 10; Value1: Unknown; Value2: 10V; TaMin_C: -55; TaMax_C: 125; AEC Category: Q200
C22 = GRM155R70J222KA01D: CAP, CERM, 2200 pF, 6.3 V, +/- 10%, X7R, 0402; Manufacturer: MuRata; Polarized: N; CompType: Capacitor; Value: 2200pF; U/M: EA; Cap_F: 0.0000000022; Tolerance_%: 10; Value1: Unknown; VDC_V: 6.3; Value2: 6.3V; TaMin_C: -55; TaMax_C: 125; AEC Category: Q200
D8 = 150060VS75000: LED, Green, SMD; Manufacturer: Wurth Elektronik; Type: AlInGaP; Vf_V: 2; Value2: 2V; Io_A: 0.02; Value1: W; U/M: EA
D9 = 150060SS75000: LED, Super Red, SMD; Manufacturer: Wurth Elektronik; Type: AlInGaP; Vf_V: 1.9; Value2: 1.9V; Io_A: 0.02; Value1: W; U/M: EA
J5 = 61300311121: as J3 on sheet TIDA-00648_DAC
J6 = 61300211121: as J1 on sheet TIDA-00648_DAC
J7 = SBH11-PBPC-D07-RA-BK: Header (Shrouded), 2.54 mm, 7x2, Gold, R/A, TH; Manufacturer: Sullins Connector Solutions; SymbolCreator: a0412235; U/M: EA
J8 J9 = SSW-110-23-F-D: Connector, Receptacle, 100mil, 10x2, Gold plated, TH; Manufacturer: Samtec; SymbolCreator: a0412235; U/M: EA
R9-R14 = CRCW04020000Z0ED: RES, 0, 5%, 0.063 W, 0402; Manufacturer: Vishay-Dale; CompType: Resistor; Value: 0; Value_Code: 0000; Tolerance_%: 5; Power_W: 0.063; Value2: 0.063W; VDC_V: 50; TempCo: 200 ppm/C; EIA_Code: E24; U/M: EA; AEC Category: Q200
R15 R24 = CRCW0402470RJNED: RES, 470, 5%, 0.063 W, 0402; Manufacturer: Vishay-Dale; CompType: Resistor; Value: 470; Value_Code: 470R; Tolerance_%: 5; Power_W: 0.063; Value2: 0.063W; VDC_V: 50; TempCo: 200 ppm/C; EIA_Code: E24; U/M: EA; AEC Category: Q200
R16-R18 = CRCW060310R0FKEA: RES, 10.0, 1%, 0.1 W, 0603; Manufacturer: Vishay-Dale; CompType: Resistor; Res_ohm: 10; Value_Code: 10R0; Tolerance_%: 1; Power_W: 0.1; Value2: 0.1W; VDC_V: 75; TempCo: 100 ppm/C; EIA_Code: E96; U/M: EA; AEC Category: Q200
R19 = CRCW040247K0JNED: RES, 47 k, 5%, 0.063 W, 0402; Manufacturer: Vishay-Dale; CompType: Resistor; Value: 47k; Res_ohm: 47000; Value_Code: 47k0; Tolerance_%: 5; Power_W: 0.063; Value2: 0.063W; VDC_V: 50; TempCo: 200 ppm/C; EIA_Code: E24; U/M: EA; AEC Category: Q200
R25 = CRCW06030000Z0EA: as R1 on sheet TIDA-00648_DAC
S1 = 434121025816: Switch, Tactile, SPST, 12 V, SMD; Manufacturer: Wurth Elektronik; SymbolCreator: a0799628; VDC_V: 12; SwitchFunction: Off-On; PositionCount: 1; CurrentRating_mA: 50
SH-J4 SH-J5 = 969102-0000-DA: as SH-J1 on sheet TIDA-00648_DAC
U3 = MSP430F5172IRSBR: 25 MHz Mixed Signal Microcontroller with 32 KB Flash, 2048 B SRAM and 29 GPIOs, -40 to 85 degC, 40-pin QFN (RSB), Green (RoHS & no Sb/Br); Alternate Manufacturer: Texas Instruments; Alternate PartNumber: Equivalent; ADC: 10-bit SAR; ADC Channels: 8; Brown Out Reset: Yes; DMA: 3; Flash(KB): 32; Frequency(MHz): 25; GPIO: 29; Multiplier: 32x32; Pin/Package: 38TSSOP, 40WQFN; SRAM(B): 2048; SubFamily: 5 Series; Timers - 16-bit: 2; USCI_A (UART/LIN/IrDA/SPI): 1

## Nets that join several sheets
GND: TIDA-00648_DAC (18 pins), TIDA-00648_MCU (18 pins)
VCC: TIDA-00648_DAC (6 pins), TIDA-00648_MCU (6 pins)
HART_TX: TIDA-00648_DAC (C13.2), TIDA-00648_MCU (J9.20)
LOOP_P: TIDA-00648_DAC (C9.1 C10.1 D7.1 R1.2), TIDA-00648_MCU (R25.1)
nDAC_ERROR: TIDA-00648_DAC (R8.2 U2.7), TIDA-00648_MCU (J8.15 R9.1)
P1.3_UCB0CLK: TIDA-00648_DAC (U2.4), TIDA-00648_MCU (J8.13 R10.1)
P1.4_UCB0SIMO: TIDA-00648_DAC (U2.5), TIDA-00648_MCU (J9.12 R11.1)
P1.5_UCB0SOMI: TIDA-00648_DAC (U2.8), TIDA-00648_MCU (J9.14 R12.1)
P2.7_SPI_CS_DAC: TIDA-00648_DAC (U2.6), TIDA-00648_MCU (J9.18 R14.2)
PG: TIDA-00648_DAC (R3.1 U1.3), TIDA-00648_MCU (R13.1)

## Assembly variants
001: not fitted C5 C13 C22 D6 FID1 FID2 FID3 LBL1 R3 R13 R23 R25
